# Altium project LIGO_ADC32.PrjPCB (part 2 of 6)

## Sheet AdcDaughterFrontEnd.SchDoc: Converter ADC Front End
size B; Engineer: Daniel Sigg; Revision: 1; SheetNumber: 6; SheetTotal: 17
Used 8 times, as channels Analog/ADC1/FrontEnd, Analog/ADC2/FrontEnd, Analog/ADC3/FrontEnd, Analog/ADC4/FrontEnd, Analog/ADC5/FrontEnd, Analog/ADC6/FrontEnd, Analog/ADC7/FrontEnd, Analog/ADC8/FrontEnd. Parts and nets are listed once, with the designators drawn on the sheet.
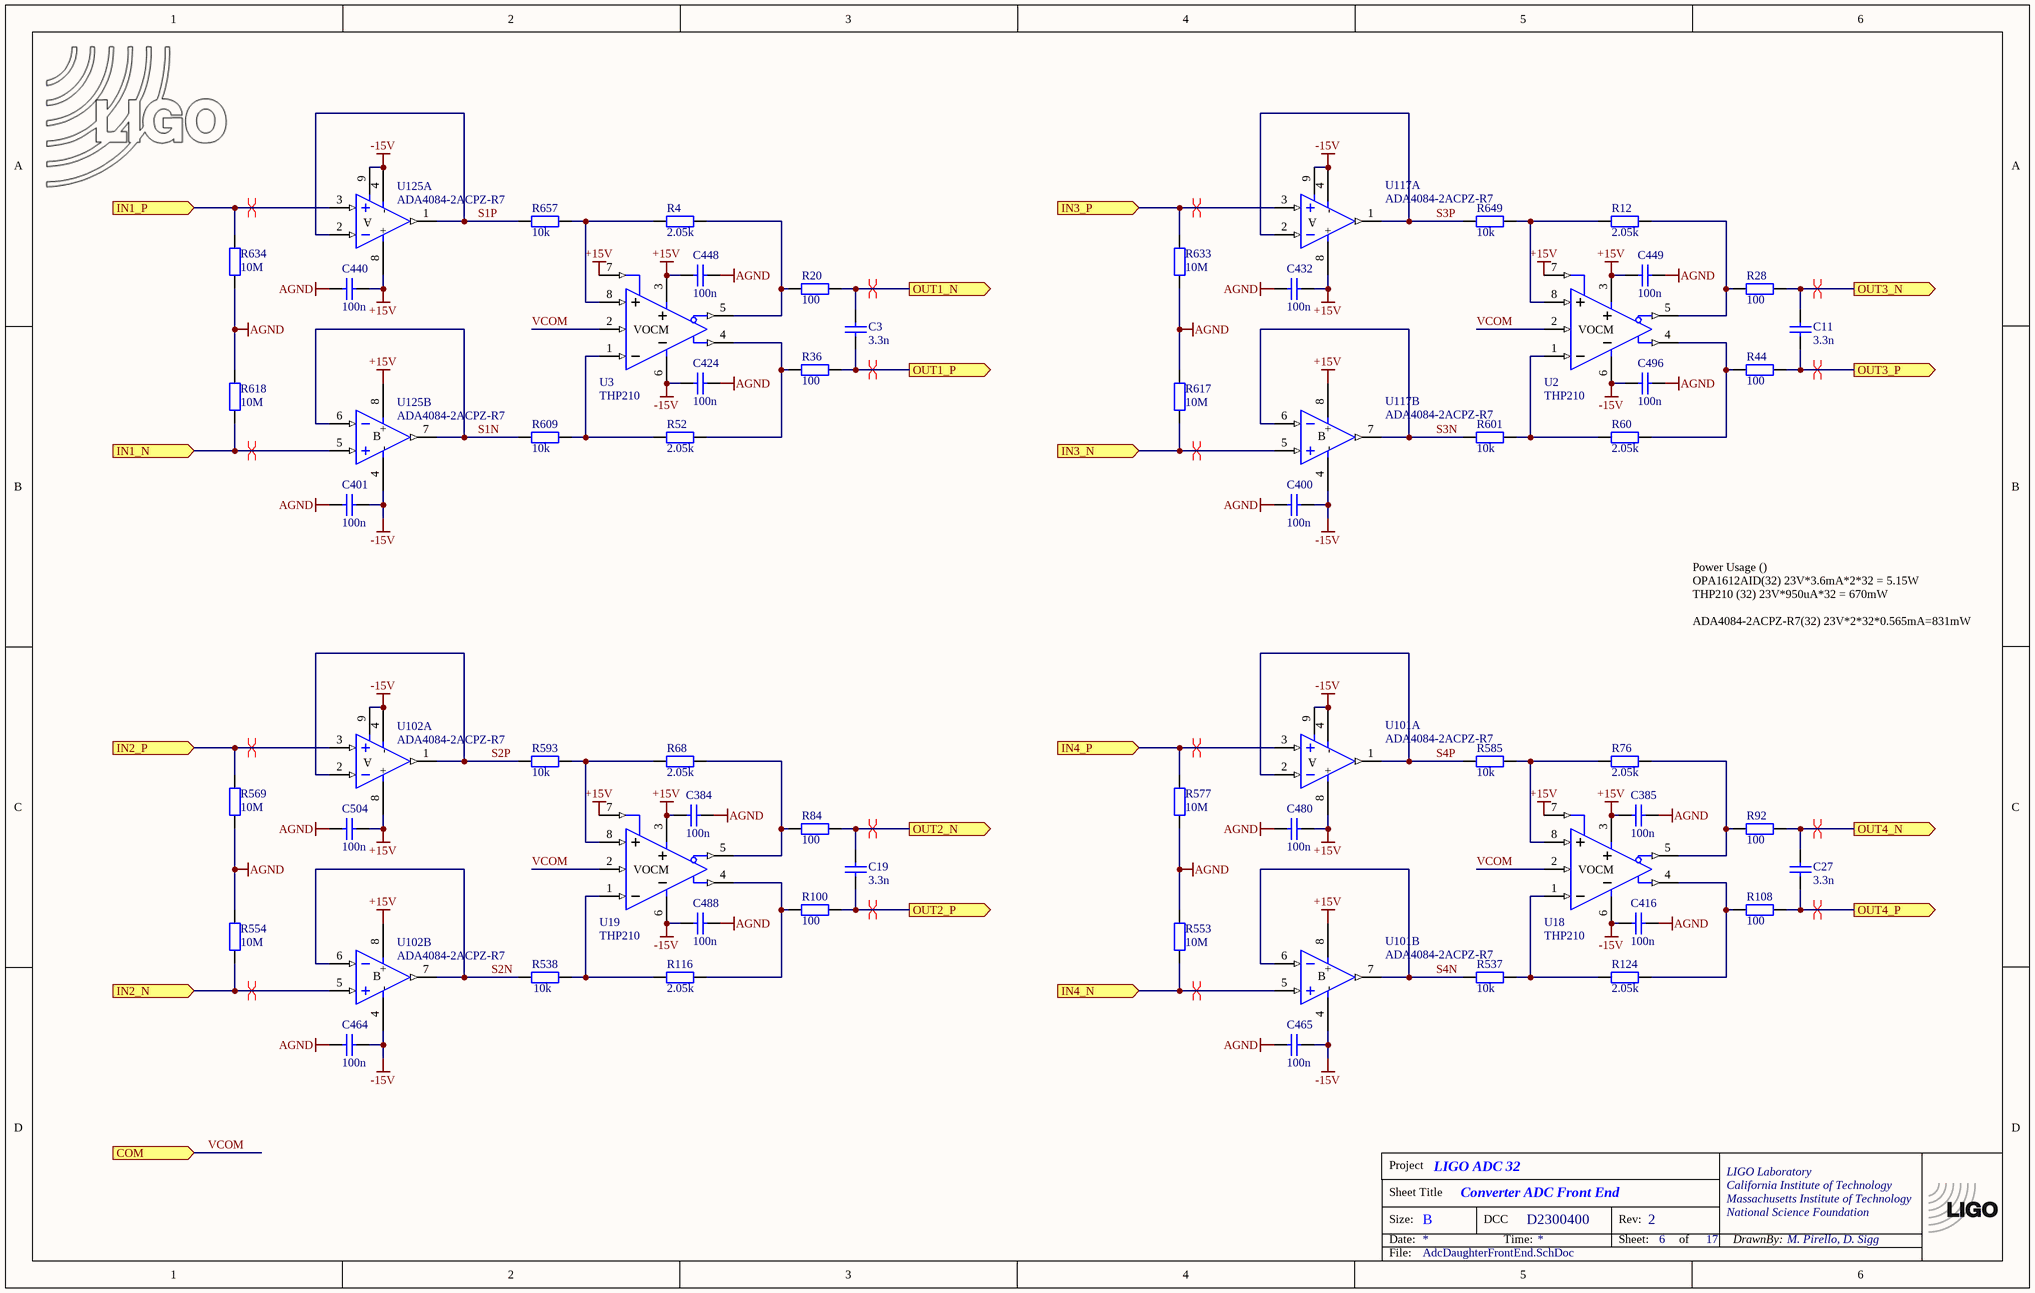
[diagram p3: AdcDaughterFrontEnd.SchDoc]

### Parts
*?  TitleBlock  (value not drawn)  (graphical)
C3  3.3n  [CC1005-0402]
C11  3.3n  [CC1005-0402]
C19  3.3n  [CC1005-0402]
C27  3.3n  [CC1005-0402]
C384  100n  [CC0603-0201]
C385  100n  [CC0603-0201]
C400  100n  [CC0603-0201]
C401  100n  [CC0603-0201]
C416  100n  [CC0603-0201]
C424  100n  [CC0603-0201]
C432  100n  [CC0603-0201]
C440  100n  [CC0603-0201]
C448  100n  [CC0603-0201]
C449  100n  [CC0603-0201]
C464  100n  [CC0603-0201]
C465  100n  [CC0603-0201]
C480  100n  [CC0603-0201]
C488  100n  [CC0603-0201]
C496  100n  [CC0603-0201]
C504  100n  [CC0603-0201]
LOGO?  LIGO logo  [LIGO_LOGO]  (value not drawn)  (graphical)
R4  2.05k  [CR1608-0603]
R12  2.05k  [CR1608-0603]
R20  100  [CR1608-0603]
R28  100  [CR1608-0603]
R36  100  [CR1608-0603]
R44  100  [CR1608-0603]
R52  2.05k  [CR1608-0603]
R60  2.05k  [CR1608-0603]
R68  2.05k  [CR1608-0603]
R76  2.05k  [CR1608-0603]
R84  100  [CR1608-0603]
R92  100  [CR1608-0603]
R100  100  [CR1608-0603]
R108  100  [CR1608-0603]
R116  2.05k  [CR1608-0603]
R124  2.05k  [CR1608-0603]
R537  10k  [CR1608-0603]
R538  10k  [CR1608-0603]
R553  10M  [CR0603-0201]
R554  10M  [CR0603-0201]
R569  10M  [CR0603-0201]
R577  10M  [CR0603-0201]
R585  10k  [CR1608-0603]
R593  10k  [CR1608-0603]
R601  10k  [CR1608-0603]
R609  10k  [CR1608-0603]
R617  10M  [CR0603-0201]
R618  10M  [CR0603-0201]
R633  10M  [CR0603-0201]
R634  10M  [CR0603-0201]
R649  10k  [CR1608-0603]
R657  10k  [CR1608-0603]
U2  THP210  [UMAX8]
U3  THP210  [UMAX8]
U18  THP210  [UMAX8]
U19  THP210  [UMAX8]
U101  ADA4084-2ACPZ-R7  [SON-8]  (parts A,B of 2)
U102  ADA4084-2ACPZ-R7  [SON-8]  (parts A,B of 2)
U117  ADA4084-2ACPZ-R7  [SON-8]  (parts A,B of 2)
U125  ADA4084-2ACPZ-R7  [SON-8]  (parts A,B of 2)

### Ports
COM (in), IN1_N (in), IN1_P (in), IN2_N (in), IN2_P (in), IN3_N (in), IN3_P (in), IN4_N (in), IN4_P (in), OUT1_N (out), OUT1_P (out), OUT2_N (out), OUT2_P (out), OUT3_N (out), OUT3_P (out), OUT4_N (out), OUT4_P (out)

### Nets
+15V: C384.2 C385.2 C432.1 C440.1 C448.2 C449.2 C480.1 C504.1 U2.3(VS+) U2.7(PD_N) U3.3(VS+) U3.7(PD_N) U18.3(VS+) U18.7(PD_N) U19.3(VS+) U19.7(PD_N) U101.8(+) U102.8(+) U117.8(+) U125.8(+)
-15V: C400.1 C401.1 C416.2 C424.2 C464.1 C465.1 C488.2 C496.2 U2.6(VS-) U3.6(VS-) U18.6(VS-) U19.6(VS-) U101.4(-) U101.9(-) U102.4(-) U102.9(-) U117.4(-) U117.9(-) U125.4(-) U125.9(-)
AGND: C384.1 C385.1 C400.2 C401.2 C416.1 C424.1 C432.2 C440.2 C448.1 C449.1 C464.2 C465.2 C480.2 C488.1 C496.1 C504.2 R553.2 R554.2 R569.1 R577.1 R617.2 R618.2 R633.1 R634.1
IN1_N: R618.1 U125.5(IN+) ; port IN1_N
IN1_P: R634.2 U125.3(IN+) ; port IN1_P
IN2_N: R554.1 U102.5(IN+) ; port IN2_N
IN2_P: R569.2 U102.3(IN+) ; port IN2_P
IN3_N: R617.1 U117.5(IN+) ; port IN3_N
IN3_P: R633.2 U117.3(IN+) ; port IN3_P
IN4_N: R553.1 U101.5(IN+) ; port IN4_N
IN4_P: R577.2 U101.3(IN+) ; port IN4_P
OUT1_N: C3.1 R20.2 ; port OUT1_N
OUT1_P: C3.2 R36.2 ; port OUT1_P
OUT2_N: C19.1 R84.2 ; port OUT2_N
OUT2_P: C19.2 R100.2 ; port OUT2_P
OUT3_N: C11.1 R28.2 ; port OUT3_N
OUT3_P: C11.2 R44.2 ; port OUT3_P
OUT4_N: C27.1 R92.2 ; port OUT4_N
OUT4_P: C27.2 R108.2 ; port OUT4_P
S1N: R609.1 U125.6(IN-) U125.7(OUT)
S1P: R657.1 U125.1 U125.2(IN-)
S2N: R538.1 U102.6(IN-) U102.7(OUT)
S2P: R593.1 U102.1 U102.2(IN-)
S3N: R601.1 U117.6(IN-) U117.7(OUT)
S3P: R649.1 U117.1 U117.2(IN-)
S4N: R537.1 U101.6(IN-) U101.7(OUT)
S4P: R585.1 U101.1 U101.2(IN-)
VCOM: U2.2(VOCM) U3.2(VOCM) U18.2(VOCM) U19.2(VOCM) ; port COM
NetR4_1: R4.1 R657.2 U3.8(VIN+)
NetR4_2: R4.2 R20.1 U3.5(VOUT-)
NetR12_1: R12.1 R649.2 U2.8(VIN+)
NetR12_2: R12.2 R28.1 U2.5(VOUT-)
NetR36_1: R36.1 R52.2 U3.4(VOUT+)
NetR44_1: R44.1 R60.2 U2.4(VOUT+)
NetR52_1: R52.1 R609.2 U3.1(VIN-)
NetR60_1: R60.1 R601.2 U2.1(VIN-)
NetR68_1: R68.1 R593.2 U19.8(VIN+)
NetR68_2: R68.2 R84.1 U19.5(VOUT-)
NetR76_1: R76.1 R585.2 U18.8(VIN+)
NetR76_2: R76.2 R92.1 U18.5(VOUT-)
NetR100_1: R100.1 R116.2 U19.4(VOUT+)
NetR108_1: R108.1 R124.2 U18.4(VOUT+)
NetR116_1: R116.1 R538.2 U19.1(VIN-)
NetR124_1: R124.1 R537.2 U18.1(VIN-)

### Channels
Analog/ADC1/FrontEnd: designators *?=*?A#2 C3=C3A C11=C11A C19=C19A C27=C27A C384=C384A C385=C385A C400=C400A C401=C401A C416=C416A C424=C424A C432=C432A C440=C440A C448=C448A C449=C449A C464=C464A C465=C465A C480=C480A C488=C488A C496=C496A C504=C504A LOGO?=LOGO?A#2 R4=R4A R12=R12A R20=R20A R28=R28A R36=R36A R44=R44A R52=R52A R60=R60A R68=R68A R76=R76A R84=R84A R92=R92A R100=R100A R108=R108A R116=R116A R124=R124A R537=R537A R538=R538A R553=R553A R554=R554A R569=R569A R577=R577A R585=R585A R593=R593A R601=R601A R609=R609A R617=R617A R618=R618A R633=R633A R634=R634A R649=R649A R657=R657A U2=U2A U3=U3A U18=U18A U19=U19A U101=U101A U102=U102A U117=U117A U125=U125A; ports COM=VCOM IN1_N=ANALOG1.A1_N IN1_P=ANALOG1.A1_P IN2_N=ANALOG1.A2_N IN2_P=ANALOG1.A2_P IN3_N=ANALOG1.A3_N IN3_P=ANALOG1.A3_P IN4_N=ANALOG1.A4_N IN4_P=ANALOG1.A4_P OUT1_N=OUT1_N_ADC1 OUT1_P=OUT1_P_ADC1 OUT2_N=OUT2_N_ADC1 OUT2_P=OUT2_P_ADC1 OUT3_N=OUT3_N_ADC1 OUT3_P=OUT3_P_ADC1 OUT4_N=OUT4_N_ADC1 OUT4_P=OUT4_P_ADC1
Analog/ADC2/FrontEnd: designators *?=*?B#2 C3=C3B C11=C11B C19=C19B C27=C27B C384=C384B C385=C385B C400=C400B C401=C401B C416=C416B C424=C424B C432=C432B C440=C440B C448=C448B C449=C449B C464=C464B C465=C465B C480=C480B C488=C488B C496=C496B C504=C504B LOGO?=LOGO?B#2 R4=R4B R12=R12B R20=R20B R28=R28B R36=R36B R44=R44B R52=R52B R60=R60B R68=R68B R76=R76B R84=R84B R92=R92B R100=R100B R108=R108B R116=R116B R124=R124B R537=R537B R538=R538B R553=R553B R554=R554B R569=R569B R577=R577B R585=R585B R593=R593B R601=R601B R609=R609B R617=R617B R618=R618B R633=R633B R634=R634B R649=R649B R657=R657B U2=U2B U3=U3B U18=U18B U19=U19B U101=U101B U102=U102B U117=U117B U125=U125B; ports COM=VCOM IN1_N=ANALOG1.A5_N IN1_P=ANALOG1.A5_P IN2_N=ANALOG1.A6_N IN2_P=ANALOG1.A6_P IN3_N=ANALOG1.A7_N IN3_P=ANALOG1.A7_P IN4_N=ANALOG1.A8_N IN4_P=ANALOG1.A8_P OUT1_N=OUT1_N_ADC2 OUT1_P=OUT1_P_ADC2 OUT2_N=OUT2_N_ADC2 OUT2_P=OUT2_P_ADC2 OUT3_N=OUT3_N_ADC2 OUT3_P=OUT3_P_ADC2 OUT4_N=OUT4_N_ADC2 OUT4_P=OUT4_P_ADC2
Analog/ADC3/FrontEnd: designators *?=*?C#2 C3=C3C C11=C11C C19=C19C C27=C27C C384=C384C C385=C385C C400=C400C C401=C401C C416=C416C C424=C424C C432=C432C C440=C440C C448=C448C C449=C449C C464=C464C C465=C465C C480=C480C C488=C488C C496=C496C C504=C504C LOGO?=LOGO?C#2 R4=R4C R12=R12C R20=R20C R28=R28C R36=R36C R44=R44C R52=R52C R60=R60C R68=R68C R76=R76C R84=R84C R92=R92C R100=R100C R108=R108C R116=R116C R124=R124C R537=R537C R538=R538C R553=R553C R554=R554C R569=R569C R577=R577C R585=R585C R593=R593C R601=R601C R609=R609C R617=R617C R618=R618C R633=R633C R634=R634C R649=R649C R657=R657C U2=U2C U3=U3C U18=U18C U19=U19C U101=U101C U102=U102C U117=U117C U125=U125C; ports COM=VCOM IN1_N=ANALOG2.A1_N IN1_P=ANALOG2.A1_P IN2_N=ANALOG2.A2_N IN2_P=ANALOG2.A2_P IN3_N=ANALOG2.A3_N IN3_P=ANALOG2.A3_P IN4_N=ANALOG2.A4_N IN4_P=ANALOG2.A4_P OUT1_N=OUT1_N_ADC3 OUT1_P=OUT1_P_ADC3 OUT2_N=OUT2_N_ADC3 OUT2_P=OUT2_P_ADC3 OUT3_N=OUT3_N_ADC3 OUT3_P=OUT3_P_ADC3 OUT4_N=OUT4_N_ADC3 OUT4_P=OUT4_P_ADC3
Analog/ADC4/FrontEnd: designators *?=*?D#2 C3=C3D C11=C11D C19=C19D C27=C27D C384=C384D C385=C385D C400=C400D C401=C401D C416=C416D C424=C424D C432=C432D C440=C440D C448=C448D C449=C449D C464=C464D C465=C465D C480=C480D C488=C488D C496=C496D C504=C504D LOGO?=LOGO?D#2 R4=R4D R12=R12D R20=R20D R28=R28D R36=R36D R44=R44D R52=R52D R60=R60D R68=R68D R76=R76D R84=R84D R92=R92D R100=R100D R108=R108D R116=R116D R124=R124D R537=R537D R538=R538D R553=R553D R554=R554D R569=R569D R577=R577D R585=R585D R593=R593D R601=R601D R609=R609D R617=R617D R618=R618D R633=R633D R634=R634D R649=R649D R657=R657D U2=U2D U3=U3D U18=U18D U19=U19D U101=U101D U102=U102D U117=U117D U125=U125D; ports COM=VCOM IN1_N=ANALOG2.A5_N IN1_P=ANALOG2.A5_P IN2_N=ANALOG2.A6_N IN2_P=ANALOG2.A6_P IN3_N=ANALOG2.A7_N IN3_P=ANALOG2.A7_P IN4_N=ANALOG2.A8_N IN4_P=ANALOG2.A8_P OUT1_N=OUT1_N_ADC4 OUT1_P=OUT1_P_ADC4 OUT2_N=OUT2_N_ADC4 OUT2_P=OUT2_P_ADC4 OUT3_N=OUT3_N_ADC4 OUT3_P=OUT3_P_ADC4 OUT4_N=OUT4_N_ADC4 OUT4_P=OUT4_P_ADC4
Analog/ADC5/FrontEnd: designators *?=*?E#2 C3=C3E C11=C11E C19=C19E C27=C27E C384=C384E C385=C385E C400=C400E C401=C401E C416=C416E C424=C424E C432=C432E C440=C440E C448=C448E C449=C449E C464=C464E C465=C465E C480=C480E C488=C488E C496=C496E C504=C504E LOGO?=LOGO?E#2 R4=R4E R12=R12E R20=R20E R28=R28E R36=R36E R44=R44E R52=R52E R60=R60E R68=R68E R76=R76E R84=R84E R92=R92E R100=R100E R108=R108E R116=R116E R124=R124E R537=R537E R538=R538E R553=R553E R554=R554E R569=R569E R577=R577E R585=R585E R593=R593E R601=R601E R609=R609E R617=R617E R618=R618E R633=R633E R634=R634E R649=R649E R657=R657E U2=U2E U3=U3E U18=U18E U19=U19E U101=U101E U102=U102E U117=U117E U125=U125E; ports COM=VCOM IN1_N=ANALOG3.A1_N IN1_P=ANALOG3.A1_P IN2_N=ANALOG3.A2_N IN2_P=ANALOG3.A2_P IN3_N=ANALOG3.A3_N IN3_P=ANALOG3.A3_P IN4_N=ANALOG3.A4_N IN4_P=ANALOG3.A4_P OUT1_N=OUT1_N_ADC5 OUT1_P=OUT1_P_ADC5 OUT2_N=OUT2_N_ADC5 OUT2_P=OUT2_P_ADC5 OUT3_N=OUT3_N_ADC5 OUT3_P=OUT3_P_ADC5 OUT4_N=OUT4_N_ADC5 OUT4_P=OUT4_P_ADC5
Analog/ADC6/FrontEnd: designators *?=*?F#2 C3=C3F C11=C11F C19=C19F C27=C27F C384=C384F C385=C385F C400=C400F C401=C401F C416=C416F C424=C424F C432=C432F C440=C440F C448=C448F C449=C449F C464=C464F C465=C465F C480=C480F C488=C488F C496=C496F C504=C504F LOGO?=LOGO?F#2 R4=R4F R12=R12F R20=R20F R28=R28F R36=R36F R44=R44F R52=R52F R60=R60F R68=R68F R76=R76F R84=R84F R92=R92F R100=R100F R108=R108F R116=R116F R124=R124F R537=R537F R538=R538F R553=R553F R554=R554F R569=R569F R577=R577F R585=R585F R593=R593F R601=R601F R609=R609F R617=R617F R618=R618F R633=R633F R634=R634F R649=R649F R657=R657F U2=U2F U3=U3F U18=U18F U19=U19F U101=U101F U102=U102F U117=U117F U125=U125F; ports COM=VCOM IN1_N=ANALOG3.A5_N IN1_P=ANALOG3.A5_P IN2_N=ANALOG3.A6_N IN2_P=ANALOG3.A6_P IN3_N=ANALOG3.A7_N IN3_P=ANALOG3.A7_P IN4_N=ANALOG3.A8_N IN4_P=ANALOG3.A8_P OUT1_N=OUT1_N_ADC6 OUT1_P=OUT1_P_ADC6 OUT2_N=OUT2_N_ADC6 OUT2_P=OUT2_P_ADC6 OUT3_N=OUT3_N_ADC6 OUT3_P=OUT3_P_ADC6 OUT4_N=OUT4_N_ADC6 OUT4_P=OUT4_P_ADC6
Analog/ADC7/FrontEnd: designators *?=*?G#2 C3=C3G C11=C11G C19=C19G C27=C27G C384=C384G C385=C385G C400=C400G C401=C401G C416=C416G C424=C424G C432=C432G C440=C440G C448=C448G C449=C449G C464=C464G C465=C465G C480=C480G C488=C488G C496=C496G C504=C504G LOGO?=LOGO?G#2 R4=R4G R12=R12G R20=R20G R28=R28G R36=R36G R44=R44G R52=R52G R60=R60G R68=R68G R76=R76G R84=R84G R92=R92G R100=R100G R108=R108G R116=R116G R124=R124G R537=R537G R538=R538G R553=R553G R554=R554G R569=R569G R577=R577G R585=R585G R593=R593G R601=R601G R609=R609G R617=R617G R618=R618G R633=R633G R634=R634G R649=R649G R657=R657G U2=U2G U3=U3G U18=U18G U19=U19G U101=U101G U102=U102G U117=U117G U125=U125G; ports COM=VCOM IN1_N=ANALOG4.A1_N IN1_P=ANALOG4.A1_P IN2_N=ANALOG4.A2_N IN2_P=ANALOG4.A2_P IN3_N=ANALOG4.A3_N IN3_P=ANALOG4.A3_P IN4_N=ANALOG4.A4_N IN4_P=ANALOG4.A4_P OUT1_N=OUT1_N_ADC7 OUT1_P=OUT1_P_ADC7 OUT2_N=OUT2_N_ADC7 OUT2_P=OUT2_P_ADC7 OUT3_N=OUT3_N_ADC7 OUT3_P=OUT3_P_ADC7 OUT4_N=OUT4_N_ADC7 OUT4_P=OUT4_P_ADC7
Analog/ADC8/FrontEnd: designators *?=*?H#2 C3=C3H C11=C11H C19=C19H C27=C27H C384=C384H C385=C385H C400=C400H C401=C401H C416=C416H C424=C424H C432=C432H C440=C440H C448=C448H C449=C449H C464=C464H C465=C465H C480=C480H C488=C488H C496=C496H C504=C504H LOGO?=LOGO?H#2 R4=R4H R12=R12H R20=R20H R28=R28H R36=R36H R44=R44H R52=R52H R60=R60H R68=R68H R76=R76H R84=R84H R92=R92H R100=R100H R108=R108H R116=R116H R124=R124H R537=R537H R538=R538H R553=R553H R554=R554H R569=R569H R577=R577H R585=R585H R593=R593H R601=R601H R609=R609H R617=R617H R618=R618H R633=R633H R634=R634H R649=R649H R657=R657H U2=U2H U3=U3H U18=U18H U19=U19H U101=U101H U102=U102H U117=U117H U125=U125H; ports COM=VCOM IN1_N=ANALOG4.A5_N IN1_P=ANALOG4.A5_P IN2_N=ANALOG4.A6_N IN2_P=ANALOG4.A6_P IN3_N=ANALOG4.A7_N IN3_P=ANALOG4.A7_P IN4_N=ANALOG4.A8_N IN4_P=ANALOG4.A8_P OUT1_N=OUT1_N_ADC8 OUT1_P=OUT1_P_ADC8 OUT2_N=OUT2_N_ADC8 OUT2_P=OUT2_P_ADC8 OUT3_N=OUT3_N_ADC8 OUT3_P=OUT3_P_ADC8 OUT4_N=OUT4_N_ADC8 OUT4_P=OUT4_P_ADC8

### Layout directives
differential pair: ANALOG1.A1_N, ANALOG1.A1_P, ANALOG1.A2_N, ANALOG1.A2_P, ANALOG1.A3_N, ANALOG1.A3_P, ANALOG1.A4_N, ANALOG1.A4_P, OUT1_N_ADC1, OUT1_P_ADC1, OUT2_N_ADC1, OUT2_P_ADC1, OUT3_N_ADC1, OUT3_P_ADC1, OUT4_N_ADC1, OUT4_P_ADC1

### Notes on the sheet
- Power Usage ()
  OPA1612AID(32) 23V*3.6mA*2*32 = 5.15W
  THP210 (32) 23V*950uA*32 = 670mW
  ADA4084-2ACPZ-R7(32) 23V*2*32*0.565mA=831mW

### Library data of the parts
C3 C11 C19 C27 = ChipCap: C0402 3.3n; Part Number: GRM1555C1H332GE01D
C384 C385 C400 C401 C416 C424 C432 C440 C448 C449 C464 C465 C480 C488 C496 C504 = ChipCap: C0201 100n; Part Number: GRM033Z71C104KE14D
LOGO? = LIGO_logo
R4 R12 R52 R60 R68 R76 R116 R124 = ChipRes1: R0603 2.05k; Part Number: RN73C1J2K05BTD
R20 R28 R36 R44 R84 R92 R100 R108 = ChipRes1: R0603 100; Part Number: ERA-3AEB101V
R537 R538 R585 R593 R601 R609 R649 R657 = ChipRes1: R0603 10k; Part Number: ERA-3ARB103V
R553 R554 R569 R577 R617 R618 R633 R634 = ChipRes1: R0201 10M; Part Number: RC0201FR-0710ML
U2 U3 U18 U19 = THP210: Fully Differential Amplifier; Part Number: THP210DR
U101 U102 U117 U125 = OPA1612AID: Dual Audio Amplifier 2 Circuit Rail-to-Rail 8-SON (3x3); Part Number: OPA1612AIDRGT

## Sheet AD32_FPGA.SchDoc: FPGA Top
size C; DocumentNumber: 6; Revision: C; SheetNumber: 12; SheetTotal: 17
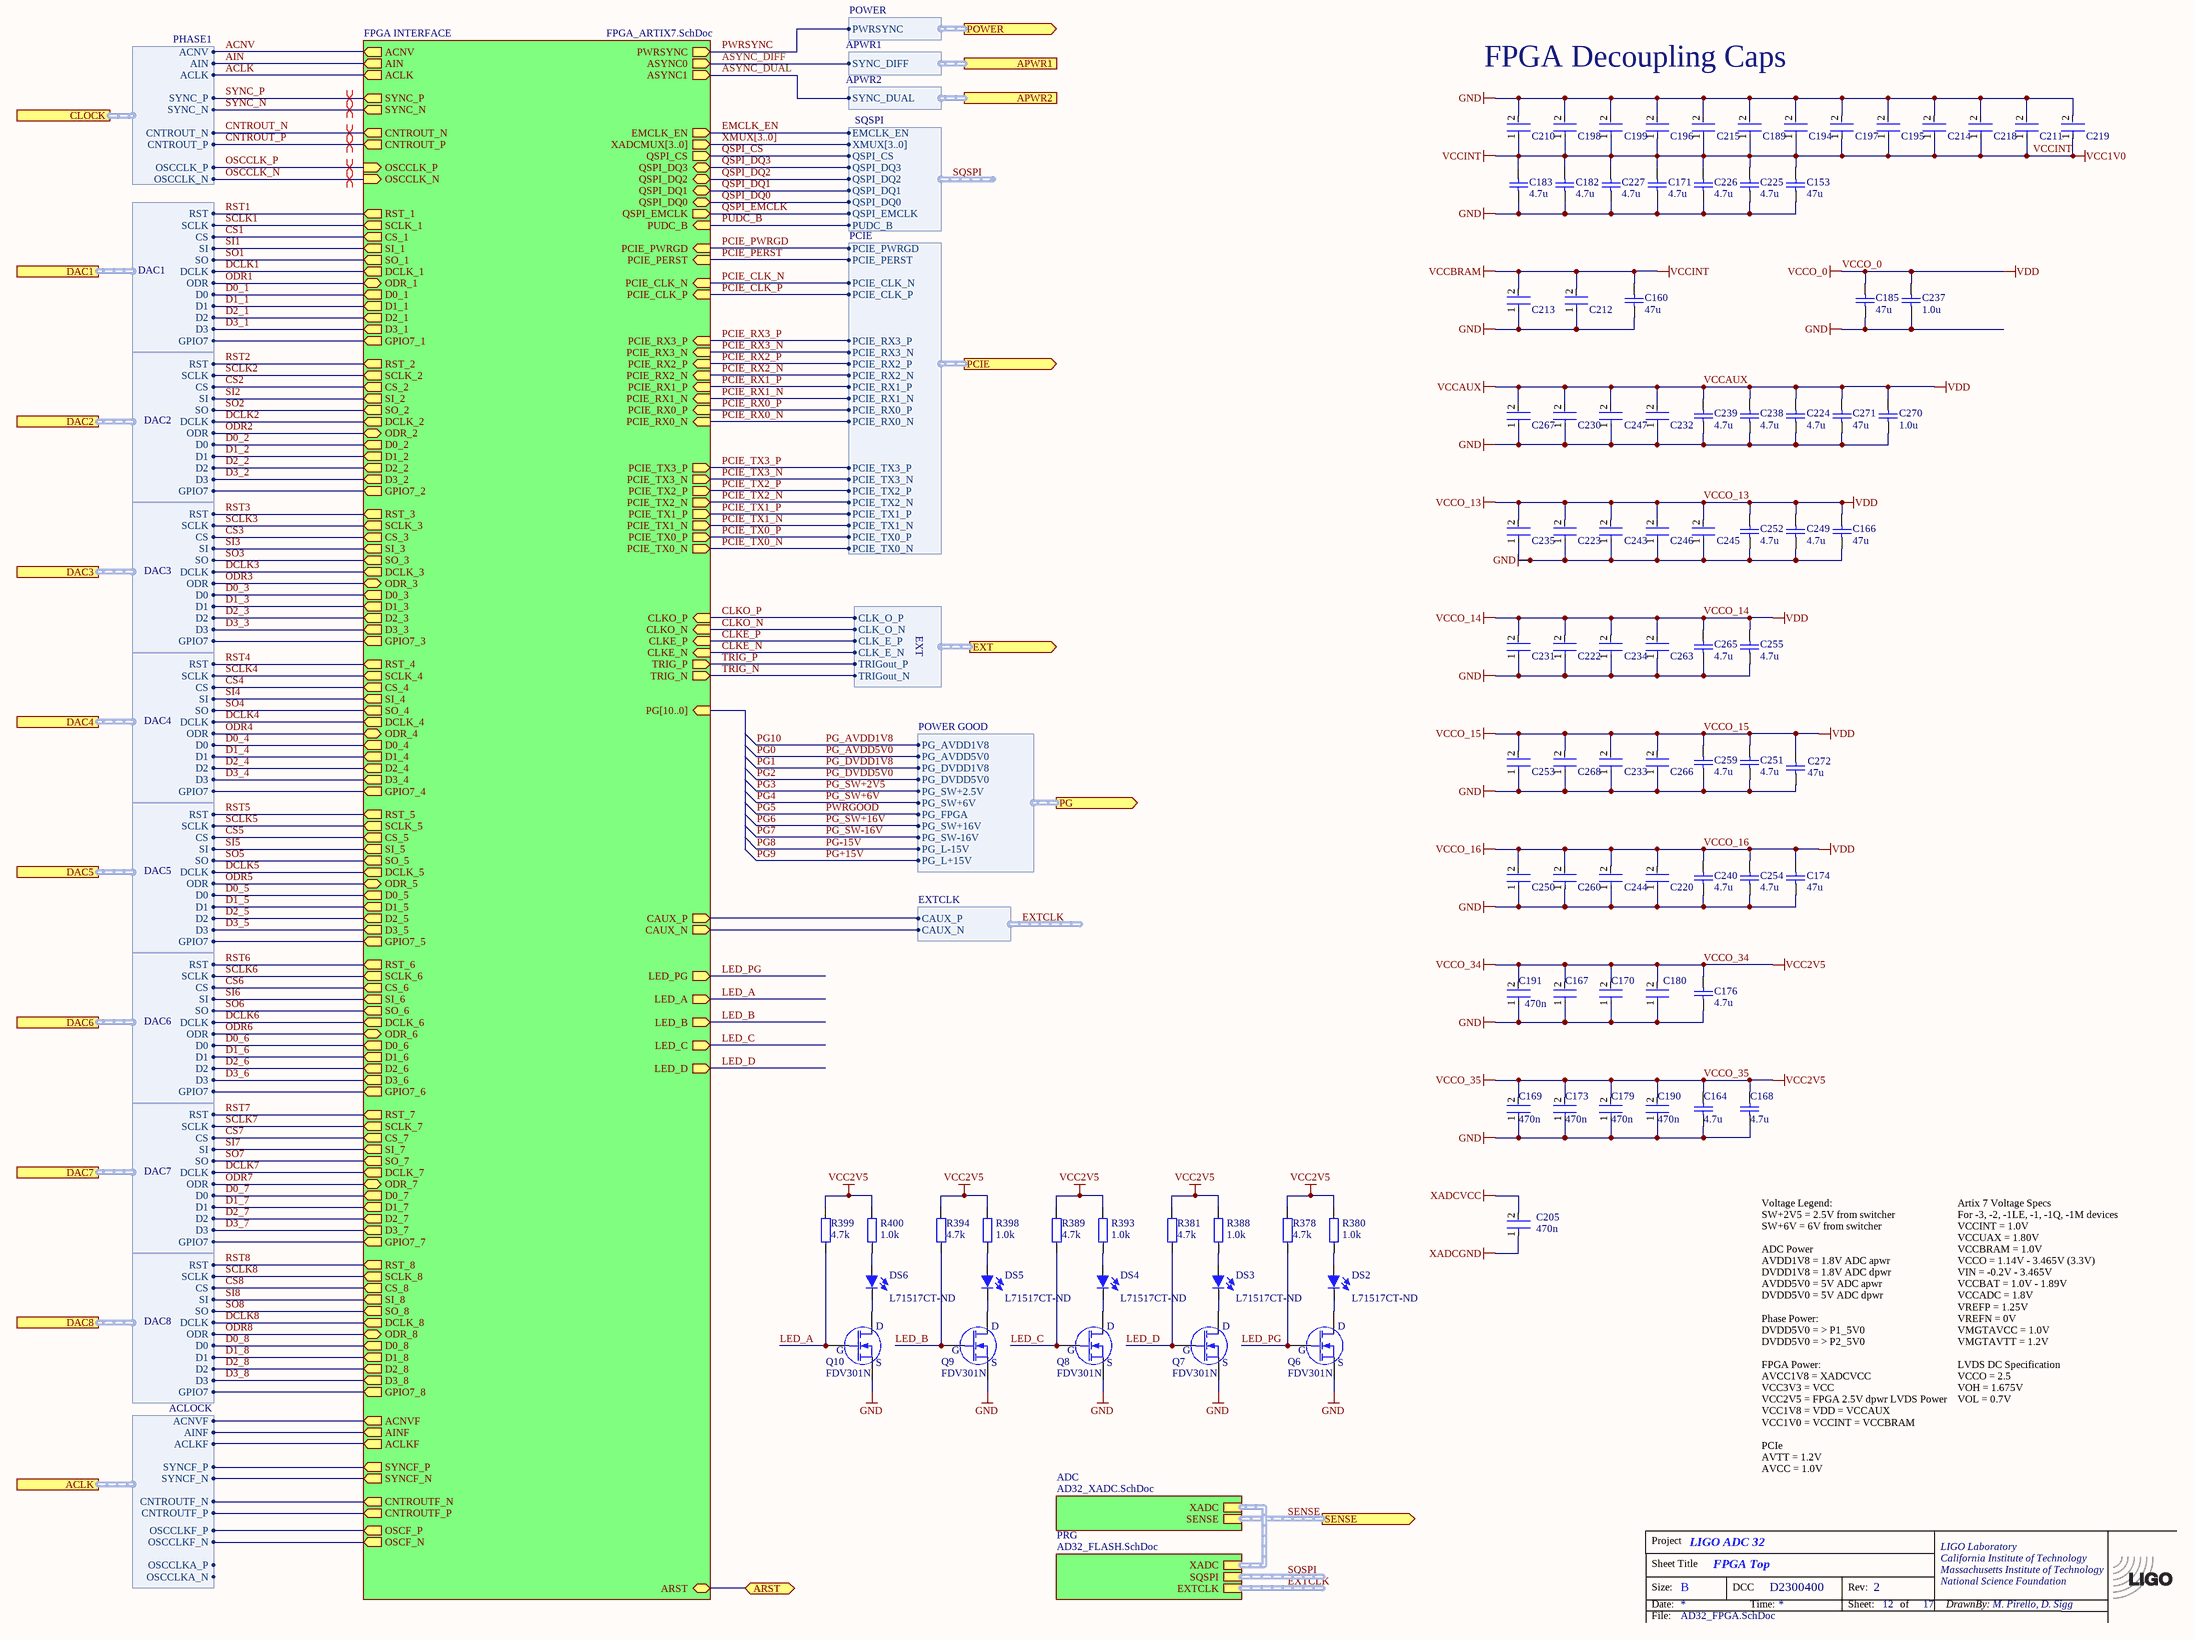
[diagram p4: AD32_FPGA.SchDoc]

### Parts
(Parts that share a designator on the sheet are numbered #1, #2 ... from top to bottom, then left to right.)
*?#3  TitleBlock  (value not drawn)  (graphical)
C153  47u  [CC3216-1206]
C160  47u  [CC3216-1206]
C164  4.7u  [CC1608-0603]
C166  47u  [CC3216-1206]
C167  470n  [FP-CL03-IPC_B]  (value not drawn)
C168  4.7u  [CC1608-0603]
C169  470n  [FP-CL03-IPC_B]
C170  470n  [FP-CL03-IPC_B]  (value not drawn)
C171  4.7u  [CC1608-0603]
C173  470n  [FP-CL03-IPC_B]
C174  47u  [CC3216-1206]
C176  4.7u  [CC1608-0603]
C179  470n  [FP-CL03-IPC_B]
C180  470n  [FP-CL03-IPC_B]  (value not drawn)
C182  4.7u  [CC1608-0603]
C183  4.7u  [CC1608-0603]
C185  47u  [CC3216-1206]
C189  470n  [FP-CL03-IPC_B]  (value not drawn)
C190  470n  [FP-CL03-IPC_B]
C191  470n  [FP-CL03-IPC_B]
C194  470n  [FP-CL03-IPC_B]  (value not drawn)
C195  470n  [FP-CL03-IPC_B]  (value not drawn)
C196  470n  [FP-CL03-IPC_B]  (value not drawn)
C197  470n  [FP-CL03-IPC_B]  (value not drawn)
C198  470n  [FP-CL03-IPC_B]  (value not drawn)
C199  470n  [FP-CL03-IPC_B]  (value not drawn)
C205  470n  [FP-CL03-IPC_B]
C210  470n  [FP-CL03-IPC_B]  (value not drawn)
C211  470n  [FP-CL03-IPC_B]  (value not drawn)
C212  470n  [FP-CL03-IPC_B]  (value not drawn)
C213  470n  [FP-CL03-IPC_B]  (value not drawn)
C214  470n  [FP-CL03-IPC_B]  (value not drawn)
C215  470n  [FP-CL03-IPC_B]  (value not drawn)
C218  470n  [FP-CL03-IPC_B]  (value not drawn)
C219  470n  [FP-CL03-IPC_B]  (value not drawn)
C220  470n  [FP-CL03-IPC_B]  (value not drawn)
C222  470n  [FP-CL03-IPC_B]  (value not drawn)
C223  470n  [FP-CL03-IPC_B]  (value not drawn)
C224  4.7u  [CC1608-0603]
C225  4.7u  [CC1608-0603]
C226  4.7u  [CC1608-0603]
C227  4.7u  [CC1608-0603]
C230  470n  [FP-CL03-IPC_B]  (value not drawn)
C231  470n  [FP-CL03-IPC_B]  (value not drawn)
C232  470n  [FP-CL03-IPC_B]  (value not drawn)
C233  470n  [FP-CL03-IPC_B]  (value not drawn)
C234  470n  [FP-CL03-IPC_B]  (value not drawn)
C235  470n  [FP-CL03-IPC_B]  (value not drawn)
C237  1.0u  [CC1608-0603]
C238  4.7u  [CC1608-0603]
C239  4.7u  [CC1608-0603]
C240  4.7u  [CC1608-0603]
C243  470n  [FP-CL03-IPC_B]  (value not drawn)
C244  470n  [FP-CL03-IPC_B]  (value not drawn)
C245  470n  [FP-CL03-IPC_B]  (value not drawn)
C246  470n  [FP-CL03-IPC_B]  (value not drawn)
C247  470n  [FP-CL03-IPC_B]  (value not drawn)
C249  4.7u  [CC1608-0603]
C250  470n  [FP-CL03-IPC_B]  (value not drawn)
C251  4.7u  [CC1608-0603]
C252  4.7u  [CC1608-0603]
C253  470n  [FP-CL03-IPC_B]  (value not drawn)
C254  4.7u  [CC1608-0603]
C255  4.7u  [CC1608-0603]
C259  4.7u  [CC1608-0603]
C260  470n  [FP-CL03-IPC_B]  (value not drawn)
C263  470n  [FP-CL03-IPC_B]  (value not drawn)
C265  4.7u  [CC1608-0603]
C266  470n  [FP-CL03-IPC_B]  (value not drawn)
C267  470n  [FP-CL03-IPC_B]  (value not drawn)
C268  470n  [FP-CL03-IPC_B]  (value not drawn)
C270  1.0u  [CC1608-0603]
C271  47u  [CC3216-1206]
C272  47u  [CC3216-1206]
DS2  Supplier Part Number 1: L71517CT-ND  [LED-0805]  (hidden comment: LED)
DS3  Supplier Part Number 1: L71517CT-ND  [LED-0805]  (hidden comment: LED)
DS4  Supplier Part Number 1: L71517CT-ND  [LED-0805]  (hidden comment: LED)
DS5  Supplier Part Number 1: L71517CT-ND  [LED-0805]  (hidden comment: LED)
DS6  Supplier Part Number 1: L71517CT-ND  [LED-0805]  (hidden comment: LED)
Q6  FDV301N  [SO-G3/C2.25]
Q7  FDV301N  [SO-G3/C2.25]
Q8  FDV301N  [SO-G3/C2.25]
Q9  FDV301N  [SO-G3/C2.25]
Q10  FDV301N  [SO-G3/C2.25]
R378  4.7k  [CR1005-0402]
R380  1.0k  [CR1005-0402]
R381  4.7k  [CR1005-0402]
R388  1.0k  [CR1005-0402]
R389  4.7k  [CR1005-0402]
R393  1.0k  [CR1005-0402]
R394  4.7k  [CR1005-0402]
R398  1.0k  [CR1005-0402]
R399  4.7k  [CR1005-0402]
R400  1.0k  [CR1005-0402]

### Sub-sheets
ADC = AD32_XADC.SchDoc: XADC (harness XADC), SENSE (harness SENSE)
FPGA INTERFACE = FPGA_ARTIX7.SchDoc: XADCMUX[3..0] (out), PWRSYNC (out), QSPI_DQ0 (bidir), QSPI_CS (out), QSPI_DQ2 (bidir), QSPI_DQ3 (bidir), QSPI_DQ1 (bidir), QSPI_EMCLK (out), PUDC_B (in), EMCLK_EN (out), PCIE_PWRGD (in), PCIE_PERST (in), PCIE_CLK_N (in), PCIE_CLK_P (in), PCIE_RX0_N (in), PCIE_TX0_P (out), PCIE_RX0_P (in), PCIE_TX0_N (out), PCIE_TX3_P (out), PCIE_TX2_P (out), PCIE_TX1_P (out), PCIE_TX3_N (out), PCIE_TX2_N (out), PCIE_TX1_N (out), PCIE_RX1_P (in), PCIE_RX2_P (in), PCIE_RX3_P (in), PCIE_RX1_N (in), PCIE_RX2_N (in), PCIE_RX3_N (in), ACNV (out), AIN (out), ACLK (out), SYNC_P (out), SYNC_N (out), CNTROUT_N (out), CNTROUT_P (out), OSCCLK_P (in), OSCCLK_N (in), SI_1 (out), RST_1 (out), D0_1 (out), SO_1 (out), DCLK_1 (out), SCLK_1 (out), CS_1 (out), ODR_1 (bidir), D1_1 (out), D2_1 (out), D3_1 (out), CLKO_P (in), CLKO_N (in), CLKE_P (in), CLKE_N (in), TRIG_P (out), TRIG_N (out), ASYNC0 (out), ASYNC1 (out), PG[10..0] (in), LED_A (out), LED_PG (out), LED_B (out), LED_C (out), LED_D (out), SI_2 (out), RST_2 (out), D0_2 (out), SO_2 (out), DCLK_2 (out), SCLK_2 (out), CS_2 (out), ODR_2 (bidir), D1_2 (out), D2_2 (out), D3_2 (out), SI_3 (out), RST_3 (out), D0_3 (out), SO_3 (out), DCLK_3 (out), SCLK_3 (out), CS_3 (out), ODR_3 (bidir), D1_3 (out), D2_3 (out), D3_3 (out), SI_4 (out), RST_4 (out), D0_4 (out), SO_4 (out), DCLK_4 (out), SCLK_4 (out), CS_4 (out), ODR_4 (bidir), D1_4 (out), D2_4 (out), D3_4 (out), SI_5 (out), RST_5 (out), D0_5 (out), SO_5 (out), DCLK_5 (out), SCLK_5 (out), CS_5 (out), ODR_5 (bidir), D1_5 (out), D2_5 (out), D3_5 (out), SI_6 (out), RST_6 (out), D0_6 (out), SO_6 (out), DCLK_6 (out), SCLK_6 (out), CS_6 (out), ODR_6 (bidir), D1_6 (out), D2_6 (out), D3_6 (out), SI_7 (out), RST_7 (out), D0_7 (out), SO_7 (out), DCLK_7 (out), SCLK_7 (out), CS_7 (out), ODR_7 (bidir), D1_7 (out), D2_7 (out), D3_7 (out), SI_8 (out), RST_8 (out), D0_8 (out), SO_8 (out), DCLK_8 (out), SCLK_8 (out), CS_8 (out), ODR_8 (bidir), D1_8 (out), D2_8 (out), D3_8 (out), OSCF_N (out), OSCF_P (out), ACNVF (out), AINF (out), ACLKF (out), SYNCF_P (out), SYNCF_N (out), CNTROUTF_N (out), CNTROUTF_P (out), ARST (bidir), CAUX_P (out), CAUX_N (out), GPIO7_8 (out), GPIO7_7 (out), GPIO7_6 (out), GPIO7_5 (out), GPIO7_4 (out), GPIO7_3 (out), GPIO7_2 (out), GPIO7_1 (out)
PRG = AD32_FLASH.SchDoc: SQSPI (harness SQSPI), XADC (harness XADC), EXTCLK (harness SQSPI)

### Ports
ACLK (harness ACLOCK), APWR1 (harness APWR1), APWR2 (harness APWR2), ARST (bidir), CLOCK (harness PHASE1), DAC1 (harness DAC1), DAC2 (harness DAC2), DAC3 (harness DAC3), DAC4 (harness DAC4), DAC5 (harness DAC5), DAC6 (harness DAC6), DAC7 (harness DAC7), DAC8 (harness DAC8), EXT (out, harness EXT), PCIE (out, harness PCIE), PG (out, harness Power good), POWER (out, harness POWER), SENSE (out, harness Power good)

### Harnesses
SQSPI: QSPI_CS, QSPI_DQ3, QSPI_DQ2, QSPI_DQ1, QSPI_DQ0, QSPI_EMCLK, PUDC_B, XMUX[3..0], EMCLK_EN
APWR1: SYNC_DIFF
APWR2: SYNC_DUAL
PHASE1: OSCCLK_N, OSCCLK_P, CNTROUT_N, CNTROUT_P, SYNC_N, SYNC_P, ACLK, ACNV, AIN
PCIE: PCIE_CLK_N, PCIE_CLK_P, PCIE_RX0_N, PCIE_RX0_P, PCIE_TX0_N, PCIE_TX0_P, PCIE_PERST, PCIE_PWRGD, PCIE_TX1_N, PCIE_TX1_P, PCIE_TX2_P, PCIE_TX2_N, PCIE_TX3_P, PCIE_TX3_N, PCIE_RX1_N, PCIE_RX1_P, PCIE_RX2_N, PCIE_RX2_P, PCIE_RX3_N, PCIE_RX3_P
EXT: CLK_O_N, CLK_E_P, CLK_E_N, CLK_O_P, TRIGout_P, TRIGout_N
POWER: PWRSYNC
DAC1: RST, SCLK, CS, SI, SO, DCLK, ODR, D0, D1, D2, D3, GPIO7
DAC2: RST, SCLK, CS, SI, SO, DCLK, ODR, D0, D1, D2, D3, GPIO7
DAC3: RST, SCLK, CS, SI, SO, DCLK, ODR, D0, D1, D2, D3, GPIO7
DAC4: RST, SCLK, CS, SI, SO, DCLK, ODR, D0, D1, D2, D3, GPIO7
DAC5: RST, SCLK, CS, SI, SO, DCLK, ODR, D0, D1, D2, D3, GPIO7
DAC6: RST, SCLK, CS, SI, SO, DCLK, ODR, D0, D1, D2, D3, GPIO7
DAC7: RST, SCLK, CS, SI, SO, DCLK, ODR, D0, D1, D2, D3, GPIO7
DAC8: RST, SCLK, CS, SI, SO, DCLK, ODR, D0, D1, D2, D3, GPIO7
ACLOCK: OSCCLKA_N, OSCCLKA_P, CNTROUTF_N, CNTROUTF_P, SYNCF_N, SYNCF_P, ACLKF, ACNVF, AINF, OSCCLKF_P, OSCCLKF_N
POWER GOOD: PG_AVDD5V0, PG_DVDD1V8, PG_DVDD5V0, PG_SW+2.5V, PG_SW+6V, PG_FPGA, PG_SW+16V, PG_SW-16V, PG_L-15V, PG_L+15V, PG_AVDD1V8
EXTCLK: CAUX_P, CAUX_N

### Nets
GND: C153.1 C160.1 C164.1 C166.1 C167.1 C168.1 C169.1 C170.1 C171.1 C173.1 C174.1 C176.1 C179.1 C180.1 C182.1 C183.1 C185.1 C189.2 C190.1 C191.1 C194.2 C195.2 C196.2 C197.2 C198.2 C199.2 C210.2 C211.2 C212.1 C213.1 C214.2 C215.2 C218.2 C219.2 C220.1 C222.1 C223.1 C224.1 C225.1 C226.1 C227.1 C230.1 C231.1 C232.1 C233.1 C234.1 C235.1 C237.1 C238.1 C239.1 C240.1 C243.1 C244.1 C245.1 C246.1 C247.1 C249.1 C250.1 C251.1 C252.1 C253.1 C254.1 C255.1 C259.1 C260.1 C263.1 C265.1 C266.1 C267.1 C268.1 C270.1 C271.1 C272.1 Q6.2(S) Q7.2(S) Q8.2(S) Q9.2(S) Q10.2(S)
VCC1V0: C153.2 C160.2 C171.2 C182.2 C183.2 C189.1 C194.1 C195.1 C196.1 C197.1 C198.1 C199.1 C210.1 C211.1 C212.2 C213.2 C214.1 C215.1 C218.1 C219.1 C225.2 C226.2 C227.2  [also labelled VCCBRAM, VCCINT]
VCC2V5: C164.2 C167.2 C168.2 C169.2 C170.2 C173.2 C176.2 C179.2 C180.2 C190.2 C191.2 R378.2 R380.1 R381.2 R388.1 R389.2 R393.1 R394.2 R398.1 R399.2 R400.1  [also labelled VCCO_34, VCCO_35]
VCCAUX: C166.2 C174.2 C185.2 C220.2 C222.2 C223.2 C224.2 C230.2 C231.2 C232.2 C233.2 C234.2 C235.2 C237.2 C238.2 C239.2 C240.2 C243.2 C244.2 C245.2 C246.2 C247.2 C249.2 C250.2 C251.2 C252.2 C253.2 C254.2 C255.2 C259.2 C260.2 C263.2 C265.2 C266.2 C267.2 C268.2 C270.2 C271.2 C272.2  [also labelled VCCO_0, VCCO_13, VCCO_14, VCCO_15, VCCO_16, VDD]  [project net VCC1V8]
XADCGND: C205.1
XADCVCC: C205.2
ACLK: sheet FPGA INTERFACE/ACLK, port CLOCK.ACLK  [project net CLOCK.ACLK]
ACLK.ACLKF: sheet FPGA INTERFACE/ACLKF, port ACLK.ACLKF
ACLK.ACNVF: sheet FPGA INTERFACE/ACNVF, port ACLK.ACNVF
ACLK.AINF: sheet FPGA INTERFACE/AINF, port ACLK.AINF
ACLK.CNTROUTF_N: sheet FPGA INTERFACE/CNTROUTF_N, port ACLK.CNTROUTF_N
ACLK.CNTROUTF_P: sheet FPGA INTERFACE/CNTROUTF_P, port ACLK.CNTROUTF_P
ACLK.OSCCLKF_N: sheet FPGA INTERFACE/OSCF_N, port ACLK.OSCCLKF_N
ACLK.OSCCLKF_P: sheet FPGA INTERFACE/OSCF_P, port ACLK.OSCCLKF_P
ACLK.SYNCF_N: sheet FPGA INTERFACE/SYNCF_N, port ACLK.SYNCF_N
ACLK.SYNCF_P: sheet FPGA INTERFACE/SYNCF_P, port ACLK.SYNCF_P
ACNV: sheet FPGA INTERFACE/ACNV, port CLOCK.ACNV  [project net CLOCK.ACNV]
ADC.GPIO7: sheet FPGA INTERFACE/GPIO7_1, port DAC1.GPIO7
ADC.GPIO7: sheet FPGA INTERFACE/GPIO7_2, port DAC2.GPIO7  [a separate net that carries the same name]
ADC.GPIO7: sheet FPGA INTERFACE/GPIO7_3, port DAC3.GPIO7  [a separate net that carries the same name]
ADC.GPIO7: sheet FPGA INTERFACE/GPIO7_4, port DAC4.GPIO7  [a separate net that carries the same name]
ADC.GPIO7: sheet FPGA INTERFACE/GPIO7_5, port DAC5.GPIO7  [a separate net that carries the same name]
ADC.GPIO7: sheet FPGA INTERFACE/GPIO7_6, port DAC6.GPIO7  [a separate net that carries the same name]
ADC.GPIO7: sheet FPGA INTERFACE/GPIO7_7, port DAC7.GPIO7  [a separate net that carries the same name]
ADC.GPIO7: sheet FPGA INTERFACE/GPIO7_8, port DAC8.GPIO7  [a separate net that carries the same name]
AIN: sheet FPGA INTERFACE/AIN, port CLOCK.AIN  [project net CLOCK.AIN]
ASYNC_DIFF: sheet FPGA INTERFACE/ASYNC0, port APWR1.SYNC_DIFF  [project net APWR1.SYNC_DIFF]
ASYNC_DUAL: sheet FPGA INTERFACE/ASYNC1, port APWR2.SYNC_DUAL  [project net APWR2.SYNC_DUAL]
CLKE_N: sheet FPGA INTERFACE/CLKE_N, port EXT.CLK_E_N
CLKE_P: sheet FPGA INTERFACE/CLKE_P, port EXT.CLK_E_P
CLKO_N: sheet FPGA INTERFACE/CLKO_N, port EXT.CLK_O_N
CLKO_P: sheet FPGA INTERFACE/CLKO_P, port EXT.CLK_O_P
CNTROUT_N: sheet FPGA INTERFACE/CNTROUT_N, port CLOCK.CNTROUT_N  [project net CLOCK.CNTROUT_N]
CNTROUT_P: sheet FPGA INTERFACE/CNTROUT_P, port CLOCK.CNTROUT_P  [project net CLOCK.CNTROUT_P]
CS1: sheet FPGA INTERFACE/CS_1, port DAC1.CS  [project net ADC.CS]
CS2: sheet FPGA INTERFACE/CS_2, port DAC2.CS  [project net ADC.CS]
CS3: sheet FPGA INTERFACE/CS_3, port DAC3.CS  [project net ADC.CS]
CS4: sheet FPGA INTERFACE/CS_4, port DAC4.CS  [project net ADC.CS]
CS5: sheet FPGA INTERFACE/CS_5, port DAC5.CS  [project net ADC.CS]
CS6: sheet FPGA INTERFACE/CS_6, port DAC6.CS  [project net ADC.CS]
CS7: sheet FPGA INTERFACE/CS_7, port DAC7.CS  [project net ADC.CS]
CS8: sheet FPGA INTERFACE/CS_8, port DAC8.CS  [project net ADC.CS]
D0_1: sheet FPGA INTERFACE/D0_1, port DAC1.D0  [project net ADC.D0]
D0_2: sheet FPGA INTERFACE/D0_2, port DAC2.D0  [project net ADC.D0]
D0_3: sheet FPGA INTERFACE/D0_3, port DAC3.D0  [project net ADC.D0]
D0_4: sheet FPGA INTERFACE/D0_4, port DAC4.D0  [project net ADC.D0]
D0_5: sheet FPGA INTERFACE/D0_5, port DAC5.D0  [project net ADC.D0]
D0_6: sheet FPGA INTERFACE/D0_6, port DAC6.D0  [project net ADC.D0]
D0_7: sheet FPGA INTERFACE/D0_7, port DAC7.D0  [project net ADC.D0]
D0_8: sheet FPGA INTERFACE/D0_8, port DAC8.D0  [project net ADC.D0]
D1_1: sheet FPGA INTERFACE/D1_1, port DAC1.D1  [project net ADC.D1]
D1_2: sheet FPGA INTERFACE/D1_2, port DAC2.D1  [project net ADC.D1]
D1_3: sheet FPGA INTERFACE/D1_3, port DAC3.D1  [project net ADC.D1]
D1_4: sheet FPGA INTERFACE/D1_4, port DAC4.D1  [project net ADC.D1]
D1_5: sheet FPGA INTERFACE/D1_5, port DAC5.D1  [project net ADC.D1]
D1_6: sheet FPGA INTERFACE/D1_6, port DAC6.D1  [project net ADC.D1]
D1_7: sheet FPGA INTERFACE/D1_7, port DAC7.D1  [project net ADC.D1]
D1_8: sheet FPGA INTERFACE/D1_8, port DAC8.D1  [project net ADC.D1]
D2_1: sheet FPGA INTERFACE/D2_1, port DAC1.D2  [project net ADC.D2]
D2_2: sheet FPGA INTERFACE/D2_2, port DAC2.D2  [project net ADC.D2]
D2_3: sheet FPGA INTERFACE/D2_3, port DAC3.D2  [project net ADC.D2]
D2_4: sheet FPGA INTERFACE/D2_4, port DAC4.D2  [project net ADC.D2]
D2_5: sheet FPGA INTERFACE/D2_5, port DAC5.D2  [project net ADC.D2]
D2_6: sheet FPGA INTERFACE/D2_6, port DAC6.D2  [project net ADC.D2]
D2_7: sheet FPGA INTERFACE/D2_7, port DAC7.D2  [project net ADC.D2]
D2_8: sheet FPGA INTERFACE/D2_8, port DAC8.D2  [project net ADC.D2]
D3_1: sheet FPGA INTERFACE/D3_1, port DAC1.D3  [project net ADC.D3]
D3_2: sheet FPGA INTERFACE/D3_2, port DAC2.D3  [project net ADC.D3]
D3_3: sheet FPGA INTERFACE/D3_3, port DAC3.D3  [project net ADC.D3]
D3_4: sheet FPGA INTERFACE/D3_4, port DAC4.D3  [project net ADC.D3]
D3_5: sheet FPGA INTERFACE/D3_5, port DAC5.D3  [project net ADC.D3]
D3_6: sheet FPGA INTERFACE/D3_6, port DAC6.D3  [project net ADC.D3]
D3_7: sheet FPGA INTERFACE/D3_7, port DAC7.D3  [project net ADC.D3]
D3_8: sheet FPGA INTERFACE/D3_8, port DAC8.D3  [project net ADC.D3]
DCLK1: sheet FPGA INTERFACE/DCLK_1, port DAC1.DCLK  [project net ADC.DCLK]
DCLK2: sheet FPGA INTERFACE/DCLK_2, port DAC2.DCLK  [project net ADC.DCLK]
DCLK3: sheet FPGA INTERFACE/DCLK_3, port DAC3.DCLK  [project net ADC.DCLK]
DCLK4: sheet FPGA INTERFACE/DCLK_4, port DAC4.DCLK  [project net ADC.DCLK]
DCLK5: sheet FPGA INTERFACE/DCLK_5, port DAC5.DCLK  [project net ADC.DCLK]
DCLK6: sheet FPGA INTERFACE/DCLK_6, port DAC6.DCLK  [project net ADC.DCLK]
DCLK7: sheet FPGA INTERFACE/DCLK_7, port DAC7.DCLK  [project net ADC.DCLK]
DCLK8: sheet FPGA INTERFACE/DCLK_8, port DAC8.DCLK  [project net ADC.DCLK]
EMCLK_EN: sheet FPGA INTERFACE/EMCLK_EN, sheet PRG/SQSPI.EMCLK_EN  [project net SQSPI.EMCLK_EN]
EXTCLK.CAUX_N: sheet FPGA INTERFACE/CAUX_N, sheet PRG/EXTCLK.CAUX_N
EXTCLK.CAUX_P: sheet FPGA INTERFACE/CAUX_P, sheet PRG/EXTCLK.CAUX_P
LED_A: Q10.1(G) R399.1 ; sheet FPGA INTERFACE/LED_A
LED_B: Q9.1(G) R394.1 ; sheet FPGA INTERFACE/LED_B
LED_C: Q8.1(G) R389.1 ; sheet FPGA INTERFACE/LED_C
LED_D: Q7.1(G) R381.1 ; sheet FPGA INTERFACE/LED_D
LED_PG: Q6.1(G) R378.1 ; sheet FPGA INTERFACE/LED_PG
ODR1: sheet FPGA INTERFACE/ODR_1, port DAC1.ODR  [project net ADC.ODR]
ODR2: sheet FPGA INTERFACE/ODR_2, port DAC2.ODR  [project net ADC.ODR]
ODR3: sheet FPGA INTERFACE/ODR_3, port DAC3.ODR  [project net ADC.ODR]
ODR4: sheet FPGA INTERFACE/ODR_4, port DAC4.ODR  [project net ADC.ODR]
ODR5: sheet FPGA INTERFACE/ODR_5, port DAC5.ODR  [project net ADC.ODR]
ODR6: sheet FPGA INTERFACE/ODR_6, port DAC6.ODR  [project net ADC.ODR]
ODR7: sheet FPGA INTERFACE/ODR_7, port DAC7.ODR  [project net ADC.ODR]
ODR8: sheet FPGA INTERFACE/ODR_8, port DAC8.ODR  [project net ADC.ODR]
OSCCLK_N: sheet FPGA INTERFACE/OSCCLK_N, port CLOCK.OSCCLK_N  [project net CLOCK.OSCCLK_N]
OSCCLK_P: sheet FPGA INTERFACE/OSCCLK_P, port CLOCK.OSCCLK_P  [project net CLOCK.OSCCLK_P]
PCIE_CLK_N: sheet FPGA INTERFACE/PCIE_CLK_N, port PCIE.PCIE_CLK_N  [project net PCIE.PCIE_CLK_N]
PCIE_CLK_P: sheet FPGA INTERFACE/PCIE_CLK_P, port PCIE.PCIE_CLK_P  [project net PCIE.PCIE_CLK_P]
PCIE_PERST: sheet FPGA INTERFACE/PCIE_PERST, port PCIE.PCIE_PERST  [project net PCIE.PCIE_PERST]
PCIE_PWRGD: sheet FPGA INTERFACE/PCIE_PWRGD, port PCIE.PCIE_PWRGD  [project net PCIE.PCIE_PWRGD]
PCIE_RX0_N: sheet FPGA INTERFACE/PCIE_RX0_N, port PCIE.PCIE_RX0_N  [project net PCIE.PCIE_RX0_N]
PCIE_RX0_P: sheet FPGA INTERFACE/PCIE_RX0_P, port PCIE.PCIE_RX0_P  [project net PCIE.PCIE_RX0_P]
PCIE_RX1_N: sheet FPGA INTERFACE/PCIE_RX1_N, port PCIE.PCIE_RX1_N  [project net PCIE.PCIE_RX1_N]
PCIE_RX1_P: sheet FPGA INTERFACE/PCIE_RX1_P, port PCIE.PCIE_RX1_P  [project net PCIE.PCIE_RX1_P]
PCIE_RX2_N: sheet FPGA INTERFACE/PCIE_RX2_N, port PCIE.PCIE_RX2_N  [project net PCIE.PCIE_RX2_N]
PCIE_RX2_P: sheet FPGA INTERFACE/PCIE_RX2_P, port PCIE.PCIE_RX2_P  [project net PCIE.PCIE_RX2_P]
PCIE_RX3_N: sheet FPGA INTERFACE/PCIE_RX3_N, port PCIE.PCIE_RX3_N  [project net PCIE.PCIE_RX3_N]
PCIE_RX3_P: sheet FPGA INTERFACE/PCIE_RX3_P, port PCIE.PCIE_RX3_P  [project net PCIE.PCIE_RX3_P]
PCIE_TX0_N: sheet FPGA INTERFACE/PCIE_TX0_N, port PCIE.PCIE_TX0_N  [project net PCIE.PCIE_TX0_N]
PCIE_TX0_P: sheet FPGA INTERFACE/PCIE_TX0_P, port PCIE.PCIE_TX0_P  [project net PCIE.PCIE_TX0_P]
PCIE_TX1_N: sheet FPGA INTERFACE/PCIE_TX1_N, port PCIE.PCIE_TX1_N  [project net PCIE.PCIE_TX1_N]
PCIE_TX1_P: sheet FPGA INTERFACE/PCIE_TX1_P, port PCIE.PCIE_TX1_P  [project net PCIE.PCIE_TX1_P]
PCIE_TX2_N: sheet FPGA INTERFACE/PCIE_TX2_N, port PCIE.PCIE_TX2_N  [project net PCIE.PCIE_TX2_N]
PCIE_TX2_P: sheet FPGA INTERFACE/PCIE_TX2_P, port PCIE.PCIE_TX2_P  [project net PCIE.PCIE_TX2_P]
PCIE_TX3_N: sheet FPGA INTERFACE/PCIE_TX3_N, port PCIE.PCIE_TX3_N  [project net PCIE.PCIE_TX3_N]
PCIE_TX3_P: sheet FPGA INTERFACE/PCIE_TX3_P, port PCIE.PCIE_TX3_P  [project net PCIE.PCIE_TX3_P]
PUDC_B: sheet FPGA INTERFACE/PUDC_B, sheet PRG/SQSPI.PUDC_B  [project net SQSPI.PUDC_B]
PWRSYNC: sheet FPGA INTERFACE/PWRSYNC, port POWER.PWRSYNC  [project net POWER.PWRSYNC]
QSPI_CS: sheet FPGA INTERFACE/QSPI_CS, sheet PRG/SQSPI.QSPI_CS  [project net SQSPI.QSPI_CS]
QSPI_DQ0: sheet FPGA INTERFACE/QSPI_DQ0, sheet PRG/SQSPI.QSPI_DQ0  [project net SQSPI.QSPI_DQ0]
QSPI_DQ1: sheet FPGA INTERFACE/QSPI_DQ1, sheet PRG/SQSPI.QSPI_DQ1  [project net SQSPI.QSPI_DQ1]
QSPI_DQ2: sheet FPGA INTERFACE/QSPI_DQ2, sheet PRG/SQSPI.QSPI_DQ2  [project net SQSPI.QSPI_DQ2]
QSPI_DQ3: sheet FPGA INTERFACE/QSPI_DQ3, sheet PRG/SQSPI.QSPI_DQ3  [project net SQSPI.QSPI_DQ3]
QSPI_EMCLK: sheet FPGA INTERFACE/QSPI_EMCLK, sheet PRG/SQSPI.QSPI_EMCLK  [project net SQSPI.QSPI_EMCLK]
RST1: port ARST, sheet FPGA INTERFACE/RST_1, sheet FPGA INTERFACE/RST_2, sheet FPGA INTERFACE/RST_3, sheet FPGA INTERFACE/RST_4, sheet FPGA INTERFACE/RST_5, sheet FPGA INTERFACE/RST_6, sheet FPGA INTERFACE/RST_7, sheet FPGA INTERFACE/RST_8, sheet FPGA INTERFACE/ARST, port DAC1.RST, port DAC2.RST, port DAC3.RST, port DAC4.RST, port DAC5.RST, port DAC6.RST, port DAC7.RST, port DAC8.RST  [also labelled RST2, RST3, RST4, RST5, RST6, RST7, RST8]  [project net ADC.RST]
SCLK1: sheet FPGA INTERFACE/SCLK_1, port DAC1.SCLK  [project net ADC.SCLK]
SCLK2: sheet FPGA INTERFACE/SCLK_2, port DAC2.SCLK  [project net ADC.SCLK]
SCLK3: sheet FPGA INTERFACE/SCLK_3, port DAC3.SCLK  [project net ADC.SCLK]
SCLK4: sheet FPGA INTERFACE/SCLK_4, port DAC4.SCLK  [project net ADC.SCLK]
SCLK5: sheet FPGA INTERFACE/SCLK_5, port DAC5.SCLK  [project net ADC.SCLK]
SCLK6: sheet FPGA INTERFACE/SCLK_6, port DAC6.SCLK  [project net ADC.SCLK]
SCLK7: sheet FPGA INTERFACE/SCLK_7, port DAC7.SCLK  [project net ADC.SCLK]
SCLK8: sheet FPGA INTERFACE/SCLK_8, port DAC8.SCLK  [project net ADC.SCLK]
SI1: sheet FPGA INTERFACE/SI_1, port DAC1.SI  [project net ADC.SI]
SI2: sheet FPGA INTERFACE/SI_2, port DAC2.SI  [project net ADC.SI]
SI3: sheet FPGA INTERFACE/SI_3, port DAC3.SI  [project net ADC.SI]
SI4: sheet FPGA INTERFACE/SI_4, port DAC4.SI  [project net ADC.SI]
SI5: sheet FPGA INTERFACE/SI_5, port DAC5.SI  [project net ADC.SI]
SI6: sheet FPGA INTERFACE/SI_6, port DAC6.SI  [project net ADC.SI]
SI7: sheet FPGA INTERFACE/SI_7, port DAC7.SI  [project net ADC.SI]
SI8: sheet FPGA INTERFACE/SI_8, port DAC8.SI  [project net ADC.SI]
SO1: sheet FPGA INTERFACE/SO_1, port DAC1.SO  [project net ADC.SO]
SO2: sheet FPGA INTERFACE/SO_2, port DAC2.SO  [project net ADC.SO]
SO3: sheet FPGA INTERFACE/SO_3, port DAC3.SO  [project net ADC.SO]
SO4: sheet FPGA INTERFACE/SO_4, port DAC4.SO  [project net ADC.SO]
SO5: sheet FPGA INTERFACE/SO_5, port DAC5.SO  [project net ADC.SO]
SO6: sheet FPGA INTERFACE/SO_6, port DAC6.SO  [project net ADC.SO]
SO7: sheet FPGA INTERFACE/SO_7, port DAC7.SO  [project net ADC.SO]
SO8: sheet FPGA INTERFACE/SO_8, port DAC8.SO  [project net ADC.SO]
SYNC_N: sheet FPGA INTERFACE/SYNC_N, port CLOCK.SYNC_N  [project net CLOCK.SYNC_N]
SYNC_P: sheet FPGA INTERFACE/SYNC_P, port CLOCK.SYNC_P  [project net CLOCK.SYNC_P]
TRIG_N: sheet FPGA INTERFACE/TRIG_N, port EXT.TRIGout_N  [project net EXT.TRIGout_N]
TRIG_P: sheet FPGA INTERFACE/TRIG_P, port EXT.TRIGout_P  [project net EXT.TRIGout_P]
NetDS2_1: DS2.1(K) Q6.3(D)
NetDS2_2: DS2.2(A) R380.2
NetDS3_1: DS3.1(K) Q7.3(D)
NetDS3_2: DS3.2(A) R388.2
NetDS4_1: DS4.1(K) Q8.3(D)
NetDS4_2: DS4.2(A) R393.2
NetDS5_1: DS5.1(K) Q9.3(D)
NetDS5_2: DS5.2(A) R398.2
NetDS6_1: DS6.1(K) Q10.3(D)
NetDS6_2: DS6.2(A) R400.2

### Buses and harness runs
bus XMUX[3..0] = sheet FPGA INTERFACE/XADCMUX[3..0]
harness EXTCLK = sheet PRG/EXTCLK
harness SENSE = port SENSE = sheet ADC/SENSE
harness sheet ADC/XADC = sheet PRG/XADC
harness SQSPI = sheet PRG/SQSPI

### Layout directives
differential pair: CLOCK.CNTROUT_N, CLOCK.CNTROUT_P, CLOCK.OSCCLK_N, CLOCK.OSCCLK_P, CLOCK.SYNC_N, CLOCK.SYNC_P

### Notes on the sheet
- FPGA Decoupling Caps
- Voltage Legend:
  SW+2V5 = 2.5V from switcher
  SW+6V = 6V from switcher
  ADC Power
  AVDD1V8 = 1.8V ADC apwr
  DVDD1V8 = 1.8V ADC dpwr
  AVDD5V0 = 5V ADC apwr
  DVDD5V0 = 5V ADC dpwr
  Phase Power:
  DVDD5V0 = > P1_5V0
  DVDD5V0 = > P2_5V0
  FPGA Power:
  AVCC1V8 = XADCVCC
  VCC3V3 = VCC
  VCC2V5 = FPGA 2.5V dpwr LVDS Power
  VCC1V8 = VDD = VCCAUX
  VCC1V0 = VCCINT = VCCBRAM
  PCIe
  AVTT = 1.2V
  AVCC = 1.0V
- Artix 7 Voltage Specs
  For -3, -2, -1LE, -1, -1Q, -1M devices
  VCCINT = 1.0V
  VCCUAX = 1.80V
  VCCBRAM = 1.0V
  VCCO = 1.14V - 3.465V (3.3V)
  VIN = -0.2V - 3.465V
  VCCBAT = 1.0V - 1.89V
  VCCADC = 1.8V
  VREFP = 1.25V
  VREFN = 0V
  VMGTAVCC = 1.0V
  VMGTAVTT = 1.2V
  LVDS DC Specification
  VCCO = 2.5
  VOH = 1.675V
  VOL = 0.7V

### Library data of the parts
C153 C160 C166 C174 C185 C271 C272 = ChipCap: C1206 47u; Part Number: C3216X5R1E476M160AC
C164 C168 C171 C176 C182 C183 C224-C227 C238-C240 C249 C251 C252 C254 C255 C259 C265 = ChipCap: C0603 4.7u; Part Number: CL10B475KQ8NQNC
C167 C169 C170 C173 C179 C180 C189-C191 C194-C199 C205 C210-C215 C218-C220 C222 C223 C230-C235 C243-C247 C250 C253 C260 C263 C266-C268 = CMP-2010-00306-2: C0201 470n; Part Number: CL03A474KQ3NNNC
C237 C270 = ChipCap: C0603 1.0u; Part Number: CL10B105KA8NNNC
DS2-DS6 = LED: Panel mount LED
Q6-Q10 = FDV301N: FDV301N, Digital FET, N-channel, SOT23; Part Number: FDV301NCT-ND
R378 R381 R389 R394 R399 = ChipRes1: R0402 4.7k; Part Number: ERA-2AED472X
R380 R388 R393 R398 R400 = ChipRes1: R0402 1.0k; Part Number: RT0402BRD071KL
